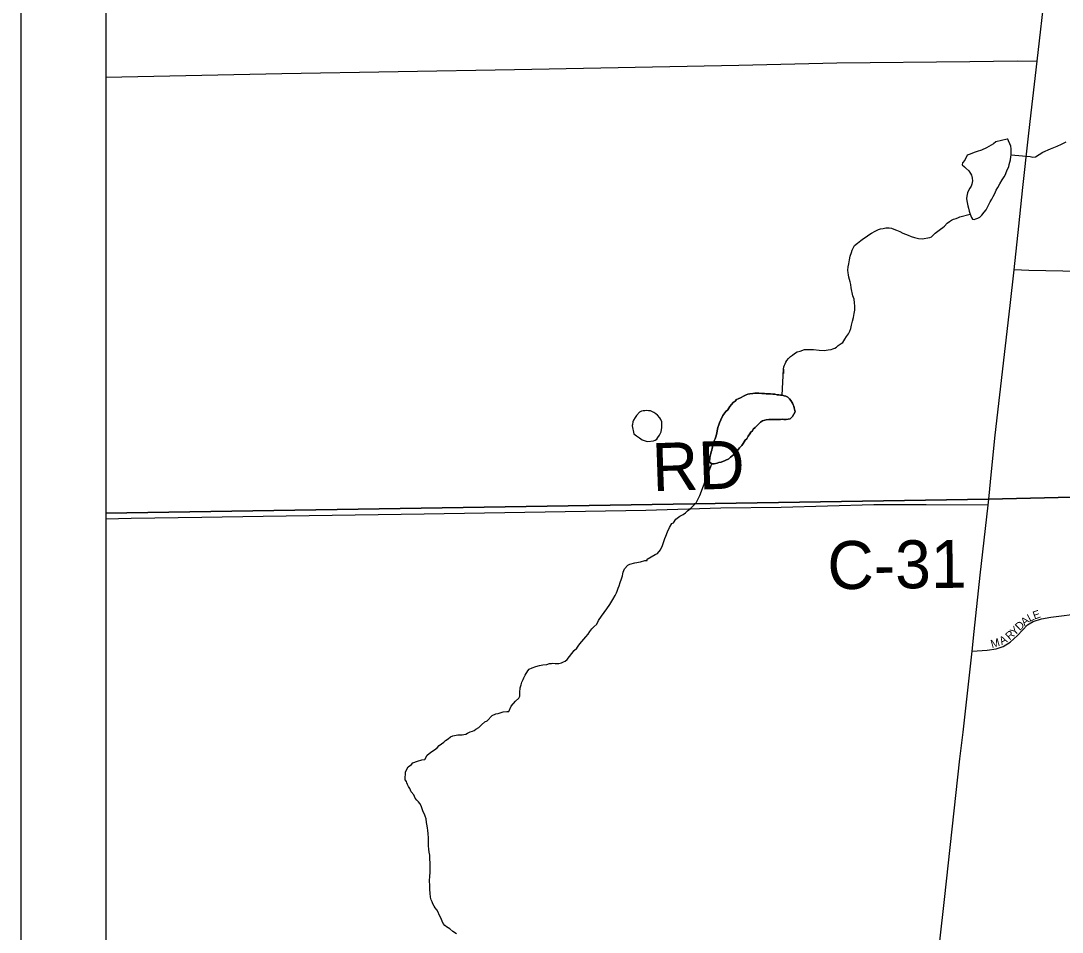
# Model space of a CAD drawing. Extents: x 0 to 34, y 0 to 22.
# Drawn here: x 2.262 to 3.494, y 19.138 to 20.216 of the extents above; entities that cross this region are included whole.
import ezdxf

# ---------------------------------------------------------------- set-up
doc = ezdxf.new("R2010")
doc.units = 0
for name, color, linetype in [('GM_X_County', 7, 'Continuous'), ('GM_X_County_Road', 7, 'Continuous'), ('GM_X_County_Road_Text', 7, 'Continuous'), ('GM_X_Minor_Lake', 7, 'Continuous'), ('GM_X_Minor_River', 7, 'Continuous'), ('GM_X_State_Route', 7, 'Continuous'), ('GM_X_Township', 7, 'Continuous'), ('GM_X_Township_Road', 7, 'Continuous'), ('GM_X_Township_Subdivision', 7, 'Continuous'), ('GM_X_Township_Subdivision_Text', 7, 'Continuous'), ('SH_Data', 7, 'Continuous')]:
    doc.layers.add(name, color=color, linetype=linetype)

msp = doc.modelspace()

# ---------------------------------------------------------------- linework, layer by layer
at = {"layer": 'GM_X_County'}
msp.add_lwpolyline([(9.1622, 14.342), (9.1622, 21.1385), (2.3622, 21.1385), (2.3622, 14.3385), (9.0003, 14.3385)], dxfattribs=at)
at = {"layer": 'GM_X_County_Road'}
for points in [[(2.3622, 20.1497), (2.5708, 20.1538), (2.8459, 20.1586), (3.1116, 20.1639), (3.2273, 20.1664), (3.3848, 20.1683), (3.4408, 20.1688), (3.4646, 20.1687)], [(3.4065, 19.6431), (3.3334, 19.6436), (3.2711, 19.6433), (3.1616, 19.6404), (3.09, 19.6394), (3.0014, 19.6367), (2.7389, 19.6325), (2.5487, 19.6296), (2.4761, 19.6283), (2.3924, 19.6271), (2.3622, 19.6267)]]:
    msp.add_lwpolyline(points, dxfattribs=at)
at = {"layer": 'GM_X_Minor_Lake'}
for points in [[(3.4158, 20.073), (3.4128, 20.0708), (3.4045, 20.0661), (3.3985, 20.0633), (3.3936, 20.0617), (3.3902, 20.0604), (3.3872, 20.0592), (3.3841, 20.058), (3.3819, 20.0572), (3.379, 20.0515), (3.3764, 20.0484), (3.3757, 20.0457), (3.3784, 20.0435), (3.3803, 20.042), (3.3838, 20.0386), (3.3858, 20.0356), (3.3869, 20.0338), (3.3874, 20.0319), (3.3878, 20.03), (3.3882, 20.027), (3.3872, 20.0231), (3.3865, 20.0208), (3.385, 20.0182), (3.3828, 20.0147), (3.3821, 20.0128), (3.3814, 20.0086), (3.3811, 20.0059), (3.3815, 20.0033), (3.3824, 19.9972), (3.3832, 19.9946), (3.3841, 19.9912), (3.3853, 19.9874), (3.3869, 19.9836), (3.3881, 19.9814), (3.39, 19.981), (3.3919, 19.9818), (3.3945, 19.9826), (3.3968, 19.9838), (3.399, 19.9862), (3.402, 19.99), (3.4042, 19.9927), (3.406, 19.9966), (3.4089, 20.0019), (3.4108, 20.0054), (3.4126, 20.0085), (3.4144, 20.0119), (3.4162, 20.0158), (3.4181, 20.0192), (3.4203, 20.0235), (3.4232, 20.0281), (3.4254, 20.0316), (3.4269, 20.0343), (3.428, 20.0369), (3.4294, 20.0408), (3.4309, 20.0435), (3.4316, 20.0461), (3.4323, 20.0492), (3.433, 20.0519), (3.4333, 20.0553), (3.434, 20.0576), (3.4339, 20.0595), (3.4339, 20.0622), (3.4338, 20.0648), (3.4334, 20.0678), (3.4322, 20.0709), (3.4306, 20.0742), (3.4298, 20.0761), (3.429, 20.0761)], [(3.429, 20.0761), (3.4158, 20.073)], [(3.1673, 19.7721), (3.1651, 19.7725), (3.1628, 19.7732), (3.1609, 19.7731), (3.1589, 19.7735), (3.157, 19.7738), (3.154, 19.7745), (3.1517, 19.7744), (3.149, 19.7748), (3.146, 19.7747), (3.1437, 19.775), (3.1418, 19.7754), (3.1387, 19.7753), (3.1353, 19.7756), (3.133, 19.7756), (3.1304, 19.7755), (3.1281, 19.7754), (3.1247, 19.775), (3.122, 19.7746), (3.1201, 19.7738), (3.1179, 19.7726), (3.1134, 19.7702), (3.1107, 19.769), (3.1088, 19.7682), (3.107, 19.7663), (3.1047, 19.7647), (3.1029, 19.7624), (3.101, 19.76), (3.0996, 19.7577), (3.0985, 19.7558), (3.0962, 19.7539), (3.0925, 19.7492), (3.09, 19.7442), (3.0885, 19.7404), (3.0878, 19.7381), (3.0867, 19.735), (3.0864, 19.7331), (3.0853, 19.7285), (3.085, 19.7266), (3.0843, 19.724), (3.0836, 19.7217), (3.0825, 19.7194), (3.0814, 19.7163), (3.0807, 19.7132), (3.08, 19.7106), (3.0797, 19.7083), (3.0786, 19.706), (3.0772, 19.6995), (3.0766, 19.6941)], [(3.0766, 19.6941), (3.0772, 19.6995), (3.0786, 19.706), (3.0797, 19.7083), (3.08, 19.7106), (3.0807, 19.7132), (3.0814, 19.7163), (3.0825, 19.7194), (3.0836, 19.7217), (3.0843, 19.724), (3.085, 19.7266), (3.0853, 19.7285), (3.0864, 19.7331), (3.0867, 19.735), (3.0878, 19.7381), (3.0885, 19.7404), (3.09, 19.7442), (3.0925, 19.7492), (3.0962, 19.7539), (3.0985, 19.7558), (3.0996, 19.7577), (3.101, 19.76), (3.1029, 19.7624), (3.1047, 19.7647), (3.107, 19.7663), (3.1088, 19.7682), (3.1107, 19.769), (3.1134, 19.7702), (3.1179, 19.7726), (3.1201, 19.7738), (3.122, 19.7746), (3.1247, 19.775), (3.1281, 19.7754), (3.1304, 19.7755), (3.133, 19.7756), (3.1353, 19.7756), (3.1387, 19.7753), (3.1418, 19.7754), (3.1437, 19.775), (3.146, 19.7747), (3.149, 19.7748), (3.1517, 19.7744), (3.154, 19.7745), (3.157, 19.7738), (3.1589, 19.7735), (3.1609, 19.7731), (3.1628, 19.7732), (3.1651, 19.7725), (3.1673, 19.7721), (3.1693, 19.771), (3.1716, 19.7688), (3.1732, 19.7669), (3.1751, 19.7639), (3.1759, 19.762), (3.1767, 19.7602), (3.1771, 19.7583), (3.178, 19.7534), (3.1751, 19.748), (3.1721, 19.7452), (3.1676, 19.7444), (3.1649, 19.7443), (3.1626, 19.7447), (3.1607, 19.7446), (3.1584, 19.7446), (3.1565, 19.7445), (3.1546, 19.7445), (3.152, 19.7444), (3.1497, 19.7444), (3.147, 19.7443), (3.144, 19.7439), (3.1421, 19.7438), (3.1394, 19.743), (3.1372, 19.7414), (3.1353, 19.7395), (3.1331, 19.7372), (3.1309, 19.7349), (3.1286, 19.7329), (3.1275, 19.731), (3.1257, 19.7294), (3.1246, 19.7275), (3.1227, 19.7248), (3.1209, 19.7217), (3.119, 19.7202), (3.1179, 19.7182), (3.1168, 19.7159), (3.115, 19.7136), (3.1124, 19.7109), (3.1098, 19.7078), (3.1072, 19.7043), (3.1016, 19.7), (3.0997, 19.6981), (3.0952, 19.6961), (3.0907, 19.6941), (3.088, 19.6936), (3.0857, 19.6928), (3.0823, 19.692), (3.0797, 19.6919), (3.0766, 19.6941)], [(3.0766, 19.6941), (3.0797, 19.6919), (3.0823, 19.692), (3.0857, 19.6928), (3.088, 19.6936), (3.0907, 19.6941), (3.0952, 19.6961), (3.0997, 19.6981), (3.1016, 19.7), (3.1072, 19.7043), (3.1098, 19.7078), (3.1124, 19.7109), (3.115, 19.7136), (3.1168, 19.7159), (3.1179, 19.7182), (3.119, 19.7202), (3.1209, 19.7217), (3.1227, 19.7248), (3.1246, 19.7275), (3.1257, 19.7294), (3.1275, 19.731), (3.1286, 19.7329), (3.1309, 19.7349), (3.1331, 19.7372), (3.1353, 19.7395), (3.1372, 19.7414), (3.1394, 19.743), (3.1421, 19.7438), (3.144, 19.7439), (3.147, 19.7443), (3.1497, 19.7444), (3.152, 19.7444), (3.1546, 19.7445), (3.1565, 19.7445), (3.1584, 19.7446), (3.1607, 19.7446), (3.1626, 19.7447), (3.1649, 19.7443), (3.1676, 19.7444), (3.1721, 19.7452), (3.1751, 19.748), (3.178, 19.7534), (3.1771, 19.7583), (3.1767, 19.7602), (3.1759, 19.762), (3.1751, 19.7639), (3.1732, 19.7669), (3.1716, 19.7688), (3.1693, 19.771), (3.1673, 19.7721)], [(3.018, 19.7465), (3.0153, 19.7494), (3.0133, 19.7513), (3.011, 19.7528), (3.0087, 19.7539), (3.0068, 19.7546), (3.0045, 19.7549), (3.0026, 19.7552), (3.0003, 19.7548), (2.9981, 19.7548), (2.9962, 19.7543), (2.9939, 19.7532), (2.9902, 19.7493), (2.9887, 19.747), (2.9869, 19.7435), (2.9862, 19.7416), (2.9855, 19.7385), (2.9851, 19.7374), (2.9851, 19.737)], [(2.9851, 19.737), (2.9872, 19.7275), (2.9903, 19.725), (2.9938, 19.7228), (2.9969, 19.7205), (2.9996, 19.7195), (3.0019, 19.7187), (3.0038, 19.7184), (3.0106, 19.7193), (3.0125, 19.7201), (3.0144, 19.7213), (3.0158, 19.7232), (3.0177, 19.7259), (3.0195, 19.7298), (3.0202, 19.7351), (3.0205, 19.7393), (3.0204, 19.7416), (3.0192, 19.7446), (3.018, 19.7465), (3.0153, 19.7494), (3.0133, 19.7513), (3.011, 19.7528), (3.0087, 19.7539), (3.0068, 19.7546), (3.0045, 19.7549), (3.0026, 19.7552), (3.0003, 19.7548), (2.9981, 19.7548), (2.9962, 19.7543), (2.9939, 19.7532), (2.9902, 19.7493), (2.9887, 19.747), (2.9869, 19.7435), (2.9862, 19.7416), (2.9855, 19.7385), (2.9851, 19.7374), (2.9851, 19.737)], [(2.9851, 19.737), (2.9872, 19.7275), (2.9903, 19.725), (2.9938, 19.7228), (2.9969, 19.7205), (2.9996, 19.7195), (3.0019, 19.7187), (3.0038, 19.7184), (3.0106, 19.7193), (3.0125, 19.7201), (3.0144, 19.7213), (3.0158, 19.7232), (3.0177, 19.7259), (3.0195, 19.7298), (3.0202, 19.7351), (3.0205, 19.7393), (3.0204, 19.7416), (3.0192, 19.7446), (3.018, 19.7465)]]:
    msp.add_lwpolyline(points, dxfattribs=at)
at = {"layer": 'GM_X_Minor_River'}
for points in [[(3.434, 20.0576), (3.4561, 20.0558), (3.4595, 20.0551), (3.4626, 20.0552), (3.4712, 20.0607), (3.4802, 20.0647), (3.4882, 20.0679), (3.4934, 20.0703), (3.4987, 20.0731)], [(3.1628, 19.7732), (3.1644, 19.804), (3.1645, 19.799), (3.1644, 19.804), (3.1647, 19.8066), (3.1654, 19.8086), (3.1665, 19.8105), (3.1672, 19.8124), (3.1683, 19.8143), (3.1702, 19.8166), (3.1728, 19.819), (3.1751, 19.8205), (3.1773, 19.8225), (3.1807, 19.8245), (3.1841, 19.8253), (3.1894, 19.8273), (3.1943, 19.8274), (3.2, 19.8272), (3.2065, 19.8266), (3.2126, 19.8263), (3.2171, 19.8268), (3.2206, 19.8272), (3.2228, 19.828), (3.2251, 19.8289), (3.227, 19.83), (3.2292, 19.832), (3.2326, 19.8343), (3.2345, 19.8355), (3.237, 19.8394), (3.2389, 19.8428), (3.2411, 19.8459), (3.2429, 19.849), (3.244, 19.8521), (3.245, 19.8563), (3.2461, 19.8609), (3.2471, 19.8651), (3.2478, 19.87), (3.2489, 19.8738), (3.2488, 19.8784), (3.2483, 19.8826), (3.2478, 19.8867), (3.2466, 19.8909), (3.2445, 19.9003), (3.244, 19.9041), (3.2432, 19.9072), (3.2424, 19.9102), (3.2416, 19.9128), (3.2411, 19.9158), (3.2407, 19.9181), (3.2406, 19.9212), (3.2409, 19.925), (3.2416, 19.9288), (3.2423, 19.9333), (3.2433, 19.9379), (3.2447, 19.9421), (3.2458, 19.9448), (3.2484, 19.9502), (3.2521, 19.9533), (3.2558, 19.9564), (3.2592, 19.9588), (3.2622, 19.9608), (3.2652, 19.9631), (3.2686, 19.9651), (3.2727, 19.9675), (3.2769, 19.9694), (3.2791, 19.9703), (3.2822, 19.9707), (3.2856, 19.9712), (3.2894, 19.9712), (3.292, 19.9709), (3.2951, 19.9698), (3.2982, 19.9684), (3.302, 19.9669), (3.3055, 19.9651), (3.3086, 19.964), (3.312, 19.9626), (3.3155, 19.9612), (3.3193, 19.9597), (3.3243, 19.9587), (3.3285, 19.9584), (3.3376, 19.9597), (3.3394, 19.9605), (3.3413, 19.9625), (3.3439, 19.9648), (3.3469, 19.9675), (3.3503, 19.9699), (3.3529, 19.9715), (3.3551, 19.9734), (3.3581, 19.9769), (3.3607, 19.9789), (3.363, 19.9804), (3.3656, 19.9816), (3.3686, 19.9825), (3.3713, 19.9837), (3.3732, 19.9845), (3.3853, 19.9874)], [(2.8755, 19.4534), (2.8797, 19.4543), (2.8843, 19.4547), (2.8873, 19.4556), (2.8896, 19.4556), (2.8915, 19.456), (2.8941, 19.4557), (2.8983, 19.4558), (2.9017, 19.4563), (2.904, 19.4575), (2.9059, 19.4586), (2.9085, 19.4606), (2.9166, 19.471), (2.9196, 19.4738), (2.9215, 19.4761), (2.9233, 19.4788), (2.9255, 19.4819), (2.9281, 19.4846), (2.9304, 19.4873), (2.933, 19.4904), (2.9352, 19.4935), (2.9374, 19.4966), (2.94, 19.4989), (2.9433, 19.5024), (2.9455, 19.5066), (2.9489, 19.5116), (2.9522, 19.5159), (2.9551, 19.5205), (2.9588, 19.5255), (2.9625, 19.5313), (2.9651, 19.5363), (2.9669, 19.5394), (2.9676, 19.5413), (2.9687, 19.5447), (2.9698, 19.5478), (2.9712, 19.5516), (2.9726, 19.5558), (2.9737, 19.5593), (2.9744, 19.562), (2.9747, 19.5639), (2.9762, 19.5677), (2.9803, 19.572), (2.9825, 19.5732), (2.9886, 19.5748), (2.995, 19.5761), (3.0003, 19.5774), (3.003, 19.5774), (3.0029, 19.5793), (3.0078, 19.5821), (3.0123, 19.5845), (3.0154, 19.586), (3.0187, 19.5903), (3.0212, 19.5953), (3.0227, 19.5999), (3.0241, 19.6037), (3.0252, 19.6064), (3.027, 19.6114), (3.0295, 19.6167), (3.0321, 19.6214), (3.034, 19.6222), (3.0369, 19.6264), (3.0418, 19.6299), (3.0456, 19.6319), (3.0482, 19.6339), (3.0508, 19.6362), (3.0538, 19.6386), (3.0609, 19.6459), (3.0627, 19.649), (3.0642, 19.6521), (3.0653, 19.6544), (3.0797, 19.6919)], [(2.7555, 19.1612), (2.7539, 19.1642), (2.7523, 19.1665), (2.7508, 19.1684), (2.7492, 19.1714), (2.7484, 19.1736), (2.7472, 19.1759), (2.7467, 19.1793), (2.7463, 19.1838), (2.7458, 19.1884), (2.7457, 19.1929), (2.7456, 19.1986), (2.7458, 19.204), (2.7461, 19.2085), (2.746, 19.2139), (2.7462, 19.2199), (2.7458, 19.2241), (2.7457, 19.2287), (2.7452, 19.2325), (2.7448, 19.2359), (2.7443, 19.24), (2.7442, 19.2446), (2.7441, 19.2492), (2.744, 19.2541), (2.7435, 19.2583), (2.7431, 19.2609), (2.7426, 19.2636), (2.7418, 19.2677), (2.7413, 19.2719), (2.7401, 19.2749), (2.7393, 19.2772), (2.7381, 19.2802), (2.7369, 19.2836), (2.7357, 19.2874), (2.7341, 19.29), (2.7325, 19.2918), (2.7306, 19.2941), (2.7286, 19.2963), (2.7267, 19.3001), (2.7239, 19.3038), (2.7223, 19.3076), (2.7207, 19.3102), (2.7195, 19.3125), (2.7187, 19.3143), (2.7183, 19.3162), (2.7168, 19.3181), (2.7169, 19.3276), (2.7202, 19.3334), (2.724, 19.3361), (2.7255, 19.3381), (2.7311, 19.3401), (2.7364, 19.3417), (2.7398, 19.3422), (2.7428, 19.3472), (2.7469, 19.3507), (2.7514, 19.3534), (2.7544, 19.3558), (2.757, 19.3585), (2.7596, 19.3605), (2.7622, 19.3624), (2.7645, 19.3647), (2.7675, 19.3667), (2.7704, 19.369), (2.7731, 19.3699), (2.775, 19.3703), (2.7788, 19.3711), (2.7811, 19.3712), (2.7841, 19.3712), (2.786, 19.3717), (2.7883, 19.3721), (2.7905, 19.3733), (2.7935, 19.3749), (2.7962, 19.3757), (2.7981, 19.3765), (2.8003, 19.3781), (2.8037, 19.38), (2.807, 19.3831), (2.8108, 19.3866), (2.8138, 19.3879), (2.8194, 19.3941), (2.8239, 19.3961), (2.8265, 19.3965), (2.8326, 19.3985), (2.8371, 19.399), (2.8394, 19.399), (2.842, 19.4052), (2.8472, 19.411), (2.8513, 19.4145), (2.8523, 19.4172), (2.8523, 19.4214), (2.8529, 19.4267), (2.854, 19.4305), (2.8547, 19.4336), (2.8561, 19.4367), (2.8572, 19.4386), (2.8587, 19.442), (2.8616, 19.447), (2.8635, 19.449), (2.8669, 19.4506), (2.8714, 19.4522), (2.8755, 19.4534)], [(2.7773, 19.1359), (2.7731, 19.1384), (2.7696, 19.1418), (2.7654, 19.144), (2.7634, 19.1458), (2.7615, 19.1481), (2.7583, 19.1556), (2.7567, 19.1582), (2.7555, 19.1612)]]:
    msp.add_lwpolyline(points, dxfattribs=at)
at = {"layer": 'GM_X_State_Route'}
for points in [[(3.454, 20.0761), (3.4563, 20.0973), (3.4646, 20.1687), (3.4743, 20.2551), (3.4745, 20.2571)], [(3.4428, 19.9731), (3.4476, 20.019), (3.454, 20.0761)], [(3.3437, 19.0776), (3.3548, 19.1765), (3.3732, 19.3429), (3.3769, 19.3744), (3.3875, 19.4703), (3.39, 19.4937), (3.3971, 19.5604), (3.4065, 19.6431), (3.4072, 19.6503), (3.4104, 19.683), (3.4148, 19.7258), (3.4326, 19.8794), (3.4375, 19.9216), (3.4428, 19.9731)]]:
    msp.add_lwpolyline(points, dxfattribs=at)
at = {"layer": 'GM_X_Township'}
for points in [[(4.3953, 21.1385), (2.3622, 21.1385), (2.3622, 19.6335)], [(2.3622, 19.6335), (3.407, 19.6503), (4.0516, 19.6654), (4.4134, 19.6764), (4.4103, 19.8926), (4.4083, 20.0336), (4.3978, 20.7562), (4.3964, 21.0758), (4.3953, 21.1385)], [(4.4298, 18.3764), (4.4274, 18.8628), (4.4176, 19.4076), (4.4134, 19.6764), (4.0516, 19.6654), (3.407, 19.6503), (2.3622, 19.6335)], [(2.3622, 19.6335), (2.3622, 14.3385), (4.4492, 14.3385)]]:
    msp.add_lwpolyline(points, dxfattribs=at)
at = {"layer": 'GM_X_Township_Road'}
msp.add_lwpolyline([(4.4103, 19.8926), (4.4007, 19.8939), (4.3818, 19.895), (4.3595, 19.8963), (4.3256, 19.8977), (4.266, 19.8998), (4.21, 19.9014), (4.1546, 19.903), (4.0463, 19.9074), (4.0137, 19.9079), (3.9685, 19.9087), (3.8968, 19.9104), (3.7978, 19.913), (3.7117, 19.9143), (3.6233, 19.9168), (3.5655, 19.9181), (3.5152, 19.9197), (3.4547, 19.9208), (3.4375, 19.9216)], dxfattribs=at)
at = {"layer": 'GM_X_Township_Subdivision'}
msp.add_lwpolyline([(3.3875, 19.4703), (3.4055, 19.4716), (3.4161, 19.4731), (3.4242, 19.476), (3.4328, 19.4809), (3.4412, 19.489), (3.4532, 19.5016), (3.4599, 19.5055), (3.4697, 19.5087), (3.4808, 19.5107), (3.5182, 19.5151), (3.5462, 19.5181), (3.6365, 19.5292), (3.6981, 19.5365), (3.7352, 19.5407)], dxfattribs=at)
at = {"layer": 'SH_Data'}
msp.add_line((2.2617, 21.2383), (2.2617, 14.2383), dxfattribs=at)

# ---------------------------------------------------------------- texts
at = {"layer": 'GM_X_County_Road_Text'}
for s, rotation, p in [('RD', 1.9711, (3.0096, 19.6595)), ('C-31', 0.6714, (3.2166, 19.5435))]:
    msp.add_text(s, height=0.05682, rotation=rotation, dxfattribs=at).set_placement(p)
at = {"layer": 'GM_X_Township_Subdivision_Text'}
for s, rotation, p in [('A', 39.3186, (3.4497, 19.4997)), ('L', 27.3959, (3.4558, 19.5047)), ('E', 19.8174, (3.4614, 19.5076)), ('Y', 44.5691, (3.438, 19.4881)), ('D', 44.5209, (3.444, 19.494)), ('M', 16.2456, (3.4111, 19.4739)), ('A', 27.3306, (3.4226, 19.4774)), ('R', 42.3164, (3.4322, 19.4828))]:
    msp.add_text(s, height=0.00947, rotation=rotation, dxfattribs=at).set_placement(p)

doc.saveas('drawing.dxf')
